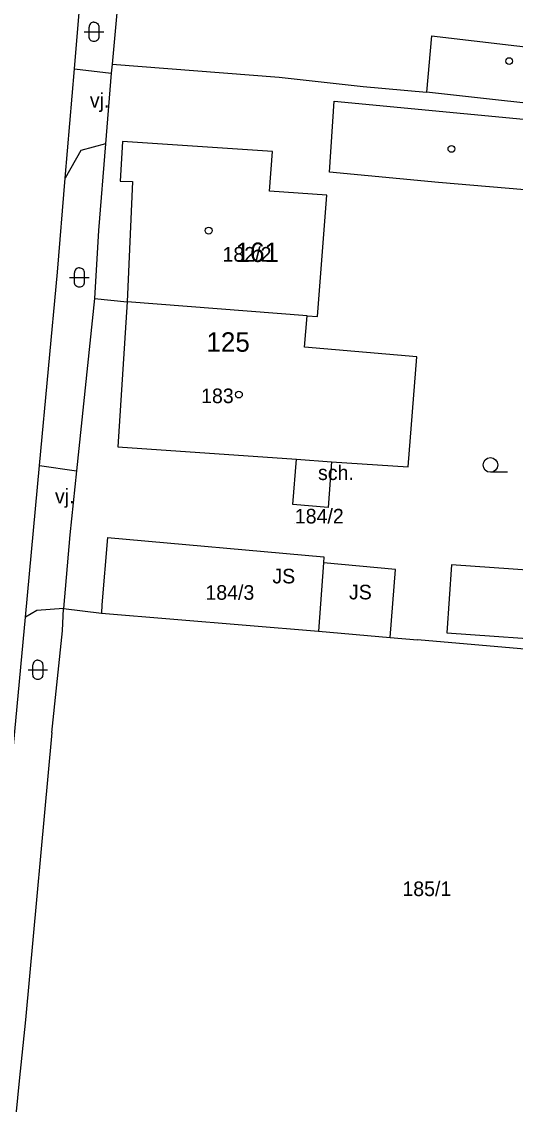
# Model space of a CAD drawing. Extents: x -836739 to -835945, y -1070775 to -1070126.
# Drawn here: x -836533 to -836507.6, y -1070547.4 to -1070491.8 of the extents above; entities that cross this region are included whole.
import ezdxf

# ---------------------------------------------------------------- set-up
doc = ezdxf.new("R2010")
doc.units = 0
for name, color, linetype in [('BodPole_mer', 7, 'Continuous'), ('Budovy_hranice', 7, 'Continuous'), ('Budovy_kody', 7, 'Continuous'), ('Doprava_hranice', 7, 'Continuous'), ('Doprava_kody', 7, 'Continuous'), ('OstPloch_kody', 7, 'Continuous'), ('RuianAdr_popis', 7, 'Continuous'), ('RuianPar_popis', 7, 'Continuous'), ('Stavby_hr_schod', 7, 'Continuous'), ('Stavby_hr_stav', 7, 'Continuous'), ('Stavby_kody', 7, 'Continuous'), ('Stavby_linie', 7, 'Continuous')]:
    doc.layers.add(name, color=color, linetype=linetype)

msp = doc.modelspace()

# ---------------------------------------------------------------- linework, layer by layer
at = {"layer": 'BodPole_mer'}
for p, q in [((-836511.95, -1070492.52), (-836511.95, -1070492.52)), ((-836530.27, -1070494.21), (-836530.27, -1070494.21)), ((-836528.34, -1070493.98), (-836528.34, -1070493.98)), ((-836528.38, -1070494.44), (-836528.38, -1070494.44)), ((-836519.76, -1070494.65), (-836519.76, -1070494.65)), ((-836515.46, -1070495.13), (-836515.46, -1070495.13)), ((-836516.94, -1070495.88), (-836516.94, -1070495.88)), ((-836512.2, -1070495.41), (-836512.2, -1070495.41)), ((-836528.67, -1070498.07), (-836528.67, -1070498.07)), ((-836527.81, -1070497.95), (-836527.81, -1070497.95)), ((-836529.94, -1070498.41), (-836529.94, -1070498.41)), ((-836520.1, -1070498.47), (-836520.1, -1070498.47)), ((-836530.74, -1070499.84), (-836530.74, -1070499.84)), ((-836517.18, -1070499.52), (-836517.18, -1070499.52)), ((-836527.93, -1070499.99), (-836527.93, -1070499.99)), ((-836527.29, -1070500.01), (-836527.29, -1070500.01)), ((-836511.59, -1070500.05), (-836511.59, -1070500.05)), ((-836520.26, -1070500.5), (-836520.26, -1070500.5)), ((-836517.32, -1070500.7), (-836517.32, -1070500.7)), ((-836529.04, -1070502.52), (-836529.04, -1070502.52)), ((-836531.14, -1070504.66), (-836531.14, -1070504.66)), ((-836529.24, -1070506.02), (-836529.24, -1070506.02)), ((-836527.57, -1070506.18), (-836527.57, -1070506.18)), ((-836518.33, -1070506.9), (-836518.33, -1070506.9)), ((-836517.79, -1070506.94), (-836517.79, -1070506.94)), ((-836518.47, -1070508.52), (-836518.47, -1070508.52)), ((-836512.7, -1070509.02), (-836512.7, -1070509.02)), ((-836528.05, -1070513.64), (-836528.05, -1070513.64)), ((-836518.87, -1070514.27), (-836518.87, -1070514.27)), ((-836532.06, -1070514.59), (-836532.06, -1070514.59)), ((-836517.08, -1070514.4), (-836517.08, -1070514.4)), ((-836513.14, -1070514.67), (-836513.14, -1070514.67)), ((-836530.17, -1070514.87), (-836530.17, -1070514.87)), ((-836519.06, -1070516.59), (-836519.06, -1070516.59)), ((-836517.25, -1070516.75), (-836517.25, -1070516.75)), ((-836530.51, -1070518.16), (-836530.51, -1070518.16)), ((-836528.57, -1070518.29), (-836528.57, -1070518.29)), ((-836517.47, -1070519.28), (-836517.47, -1070519.28)), ((-836517.49, -1070519.59), (-836517.49, -1070519.59)), ((-836510.92, -1070519.69), (-836510.92, -1070519.69)), ((-836513.8, -1070519.93), (-836513.8, -1070519.93)), ((-836532.2, -1070522.04), (-836532.2, -1070522.04)), ((-836530.84, -1070521.94), (-836530.84, -1070521.94)), ((-836528.86, -1070521.75), (-836528.86, -1070521.75)), ((-836532.78, -1070522.39), (-836532.78, -1070522.39)), ((-836528.89, -1070522.17), (-836528.89, -1070522.17)), ((-836530.88, -1070523.09), (-836530.88, -1070523.09)), ((-836517.74, -1070523.11), (-836517.74, -1070523.11)), ((-836511.16, -1070523.19), (-836511.16, -1070523.19)), ((-836514.07, -1070523.42), (-836514.07, -1070523.42)), ((-836512.66, -1070523.54), (-836512.66, -1070523.54)), ((-836508.54, -1070523.9), (-836508.54, -1070523.9)), ((-836531.43, -1070528.31), (-836531.43, -1070528.31))]:
    msp.add_line(p, q, dxfattribs=at)
at = {"layer": 'Budovy_hranice'}
msp.add_line((-836511.95, -1070492.52), (-836512.2, -1070495.41), dxfattribs=at)
for points in [[(-836511.95, -1070492.52), (-836492.81, -1070494.76), (-836493.12, -1070497.51), (-836495.07, -1070497.31), (-836512.2, -1070495.41)], [(-836517.18, -1070499.52), (-836516.94, -1070495.88), (-836497.33, -1070497.74), (-836497.7, -1070501.24), (-836511.59, -1070500.05), (-836517.18, -1070499.52)], [(-836518.33, -1070506.9), (-836517.79, -1070506.94), (-836517.32, -1070500.7), (-836520.26, -1070500.5), (-836520.1, -1070498.47), (-836527.81, -1070497.95), (-836527.93, -1070499.99), (-836527.29, -1070500.01), (-836527.57, -1070506.18)], [(-836528.05, -1070513.64), (-836518.87, -1070514.27), (-836517.08, -1070514.4), (-836513.14, -1070514.67), (-836512.7, -1070509.02), (-836518.47, -1070508.52), (-836518.33, -1070506.9), (-836527.57, -1070506.18), (-836528.05, -1070513.64)]]:
    msp.add_lwpolyline(points, dxfattribs=at)
at = {"layer": 'Budovy_kody'}
for centre in [(-836507.96, -1070493.82), (-836510.92, -1070498.33), (-836523.38, -1070502.53), (-836521.83, -1070510.95)]:
    msp.add_circle(centre, 0.175, dxfattribs=at)
at = {"layer": 'Doprava_hranice'}
for p, q in [((-836530.27, -1070494.21), (-836528.38, -1070494.44)), ((-836532.06, -1070514.59), (-836530.17, -1070514.87))]:
    msp.add_line(p, q, dxfattribs=at)
for points in [[(-836535.55, -1070551.78), (-836534.99, -1070545.87), (-836532.78, -1070522.39), (-836532.06, -1070514.59), (-836531.14, -1070504.66), (-836530.74, -1070499.84), (-836530.27, -1070494.21), (-836529.99, -1070490.91), (-836529.84, -1070489.08), (-836529.13, -1070478.74)], [(-836528.67, -1070498.07), (-836529.94, -1070498.41), (-836530.74, -1070499.84)], [(-836530.84, -1070521.94), (-836532.2, -1070522.04), (-836532.78, -1070522.39)]]:
    msp.add_lwpolyline(points, dxfattribs=at)
at = {"layer": 'OstPloch_kody'}
for p, q in [((-836529.77, -1070492.32), (-836528.77, -1070492.32)), ((-836529.52, -1070492.57), (-836529.52, -1070492.07)), ((-836529.02, -1070492.07), (-836529.02, -1070492.57)), ((-836530.27, -1070505.19), (-836530.27, -1070504.69)), ((-836529.77, -1070504.69), (-836529.77, -1070505.19)), ((-836530.52, -1070504.94), (-836529.52, -1070504.94)), ((-836508.045, -1070514.94), (-836508.92, -1070514.94)), ((-836532.4, -1070525.34), (-836532.4, -1070524.84)), ((-836531.9, -1070524.84), (-836531.9, -1070525.34)), ((-836532.65, -1070525.09), (-836531.65, -1070525.09))]:
    msp.add_line(p, q, dxfattribs=at)
for points in [[(-836529.27, -1070491.82), (-836529.315, -1070491.824), (-836529.362, -1070491.838), (-836529.407, -1070491.861), (-836529.447, -1070491.893), (-836529.479, -1070491.933), (-836529.502, -1070491.978), (-836529.516, -1070492.025), (-836529.52, -1070492.07)], [(-836529.27, -1070491.82), (-836529.225, -1070491.824), (-836529.178, -1070491.838), (-836529.133, -1070491.861), (-836529.093, -1070491.893), (-836529.061, -1070491.933), (-836529.038, -1070491.978), (-836529.024, -1070492.025), (-836529.02, -1070492.07)], [(-836529.27, -1070492.82), (-836529.315, -1070492.816), (-836529.362, -1070492.802), (-836529.407, -1070492.779), (-836529.447, -1070492.747), (-836529.479, -1070492.707), (-836529.502, -1070492.662), (-836529.516, -1070492.615), (-836529.52, -1070492.57)], [(-836529.02, -1070492.57), (-836529.024, -1070492.615), (-836529.038, -1070492.662), (-836529.061, -1070492.707), (-836529.093, -1070492.747), (-836529.133, -1070492.779), (-836529.178, -1070492.802), (-836529.225, -1070492.816), (-836529.27, -1070492.82)], [(-836530.02, -1070504.44), (-836530.065, -1070504.444), (-836530.112, -1070504.458), (-836530.157, -1070504.481), (-836530.197, -1070504.513), (-836530.229, -1070504.553), (-836530.252, -1070504.598), (-836530.266, -1070504.645), (-836530.27, -1070504.69)], [(-836530.02, -1070504.44), (-836529.975, -1070504.444), (-836529.928, -1070504.458), (-836529.883, -1070504.481), (-836529.843, -1070504.513), (-836529.811, -1070504.553), (-836529.788, -1070504.598), (-836529.774, -1070504.645), (-836529.77, -1070504.69)], [(-836530.02, -1070505.44), (-836530.065, -1070505.436), (-836530.112, -1070505.422), (-836530.157, -1070505.399), (-836530.197, -1070505.367), (-836530.229, -1070505.327), (-836530.252, -1070505.282), (-836530.266, -1070505.235), (-836530.27, -1070505.19)], [(-836529.77, -1070505.19), (-836529.774, -1070505.235), (-836529.788, -1070505.282), (-836529.811, -1070505.327), (-836529.843, -1070505.367), (-836529.883, -1070505.399), (-836529.928, -1070505.422), (-836529.975, -1070505.436), (-836530.02, -1070505.44)], [(-836532.15, -1070524.59), (-836532.195, -1070524.594), (-836532.242, -1070524.608), (-836532.287, -1070524.631), (-836532.327, -1070524.663), (-836532.359, -1070524.703), (-836532.382, -1070524.748), (-836532.396, -1070524.795), (-836532.4, -1070524.84)], [(-836532.15, -1070524.59), (-836532.105, -1070524.594), (-836532.058, -1070524.608), (-836532.013, -1070524.631), (-836531.973, -1070524.663), (-836531.941, -1070524.703), (-836531.918, -1070524.748), (-836531.904, -1070524.795), (-836531.9, -1070524.84)], [(-836532.15, -1070525.59), (-836532.195, -1070525.586), (-836532.242, -1070525.572), (-836532.287, -1070525.549), (-836532.327, -1070525.517), (-836532.359, -1070525.477), (-836532.382, -1070525.432), (-836532.396, -1070525.385), (-836532.4, -1070525.34)], [(-836531.9, -1070525.34), (-836531.904, -1070525.385), (-836531.918, -1070525.432), (-836531.941, -1070525.477), (-836531.973, -1070525.517), (-836532.013, -1070525.549), (-836532.058, -1070525.572), (-836532.105, -1070525.586), (-836532.15, -1070525.59)]]:
    msp.add_lwpolyline(points, dxfattribs=at)
msp.add_ellipse((-836508.92, -1070514.565), major_axis=(0.375, 0), ratio=0.999999, dxfattribs=at)
at = {"layer": 'RuianAdr_popis'}
for p, q in [((-836522, -1070504.14), (-836522, -1070504.14)), ((-836523.5, -1070508.75), (-836523.5, -1070508.75))]:
    msp.add_line(p, q, dxfattribs=at)
at = {"layer": 'RuianPar_popis'}
for p, q in [((-836522.67, -1070504.12), (-836522.67, -1070504.12)), ((-836523.77, -1070511.39), (-836523.77, -1070511.39)), ((-836518.96, -1070517.57), (-836518.96, -1070517.57)), ((-836523.55, -1070521.49), (-836523.55, -1070521.49)), ((-836513.44, -1070536.71), (-836513.44, -1070536.71))]:
    msp.add_line(p, q, dxfattribs=at)
at = {"layer": 'Stavby_hr_schod'}
msp.add_lwpolyline([(-836517.08, -1070514.4), (-836517.25, -1070516.75), (-836519.06, -1070516.59), (-836518.87, -1070514.27)], dxfattribs=at)
at = {"layer": 'Stavby_hr_stav'}
for points in [[(-836528.57, -1070518.29), (-836517.47, -1070519.28), (-836517.49, -1070519.59), (-836517.74, -1070523.11)], [(-836514.07, -1070523.42), (-836513.8, -1070519.93), (-836517.49, -1070519.59)], [(-836504.84, -1070523.63), (-836504.59, -1070520.14), (-836510.92, -1070519.69), (-836511.16, -1070523.19), (-836504.84, -1070523.63)]]:
    msp.add_lwpolyline(points, dxfattribs=at)
at = {"layer": 'Stavby_linie'}
for p, q in [((-836515.46, -1070495.13), (-836512.2, -1070495.41)), ((-836528.67, -1070498.07), (-836529.04, -1070502.52)), ((-836529.04, -1070502.52), (-836529.24, -1070506.02)), ((-836529.24, -1070506.02), (-836527.57, -1070506.18)), ((-836530.51, -1070518.16), (-836530.84, -1070521.94)), ((-836530.88, -1070523.09), (-836530.84, -1070521.94)), ((-836530.84, -1070521.94), (-836528.89, -1070522.17)), ((-836531.43, -1070528.31), (-836530.88, -1070523.09))]:
    msp.add_line(p, q, dxfattribs=at)
for points in [[(-836526.89, -1070478.47), (-836527.9, -1070489.26), (-836528.06, -1070490.96), (-836528.34, -1070493.98)], [(-836528.34, -1070493.98), (-836528.38, -1070494.44), (-836528.67, -1070498.07)], [(-836528.34, -1070493.98), (-836519.76, -1070494.65), (-836515.46, -1070495.13)], [(-836529.24, -1070506.02), (-836530.17, -1070514.87), (-836530.51, -1070518.16)], [(-836528.57, -1070518.29), (-836528.86, -1070521.75), (-836528.89, -1070522.17), (-836517.74, -1070523.11), (-836514.07, -1070523.42), (-836512.66, -1070523.54)], [(-836493.38, -1070525.22), (-836508.54, -1070523.9), (-836512.66, -1070523.54)], [(-836531.43, -1070528.31), (-836532.79, -1070543.06), (-836533.11, -1070546.2), (-836533.66, -1070551.8), (-836535.45, -1070569.74)]]:
    msp.add_lwpolyline(points, dxfattribs=at)

# ---------------------------------------------------------------- texts
at = {"layer": 'Doprava_kody'}
for p in [(-836529.48, -1070496.21), (-836531.27, -1070516.54)]:
    msp.add_text('vj.', height=0.75, dxfattribs=at).set_placement(p)
at = {"layer": 'RuianAdr_popis'}
for s, p in [('161', (-836522, -1070504.14)), ('125', (-836523.5, -1070508.75))]:
    msp.add_text(s, height=1, dxfattribs=at).set_placement(p)
at = {"layer": 'RuianPar_popis'}
for s, p in [('182/2', (-836522.67, -1070504.12)), ('183', (-836523.77, -1070511.39)), ('184/2', (-836518.96, -1070517.57)), ('184/3', (-836523.55, -1070521.49)), ('185/1', (-836513.44, -1070536.71))]:
    msp.add_text(s, height=0.75, dxfattribs=at).set_placement(p)
at = {"layer": 'Stavby_kody'}
for s, p in [('sch.', (-836517.77, -1070515.34)), ('JS', (-836520.11, -1070520.65)), ('JS', (-836516.18, -1070521.47))]:
    msp.add_text(s, height=0.75, dxfattribs=at).set_placement(p)

doc.saveas('drawing.dxf')
